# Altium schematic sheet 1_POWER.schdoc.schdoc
size 426 x 302 mm; Symbol: Sheet_A3_Whycan; Device: Sheet_A3; @Project Name: Avaota A1; REV: 1.0; Company: YuzukiHD; Draw By: GloomyGhost; @Update Date: 2024-03-22; @Page No: 3; @Page Count: 13
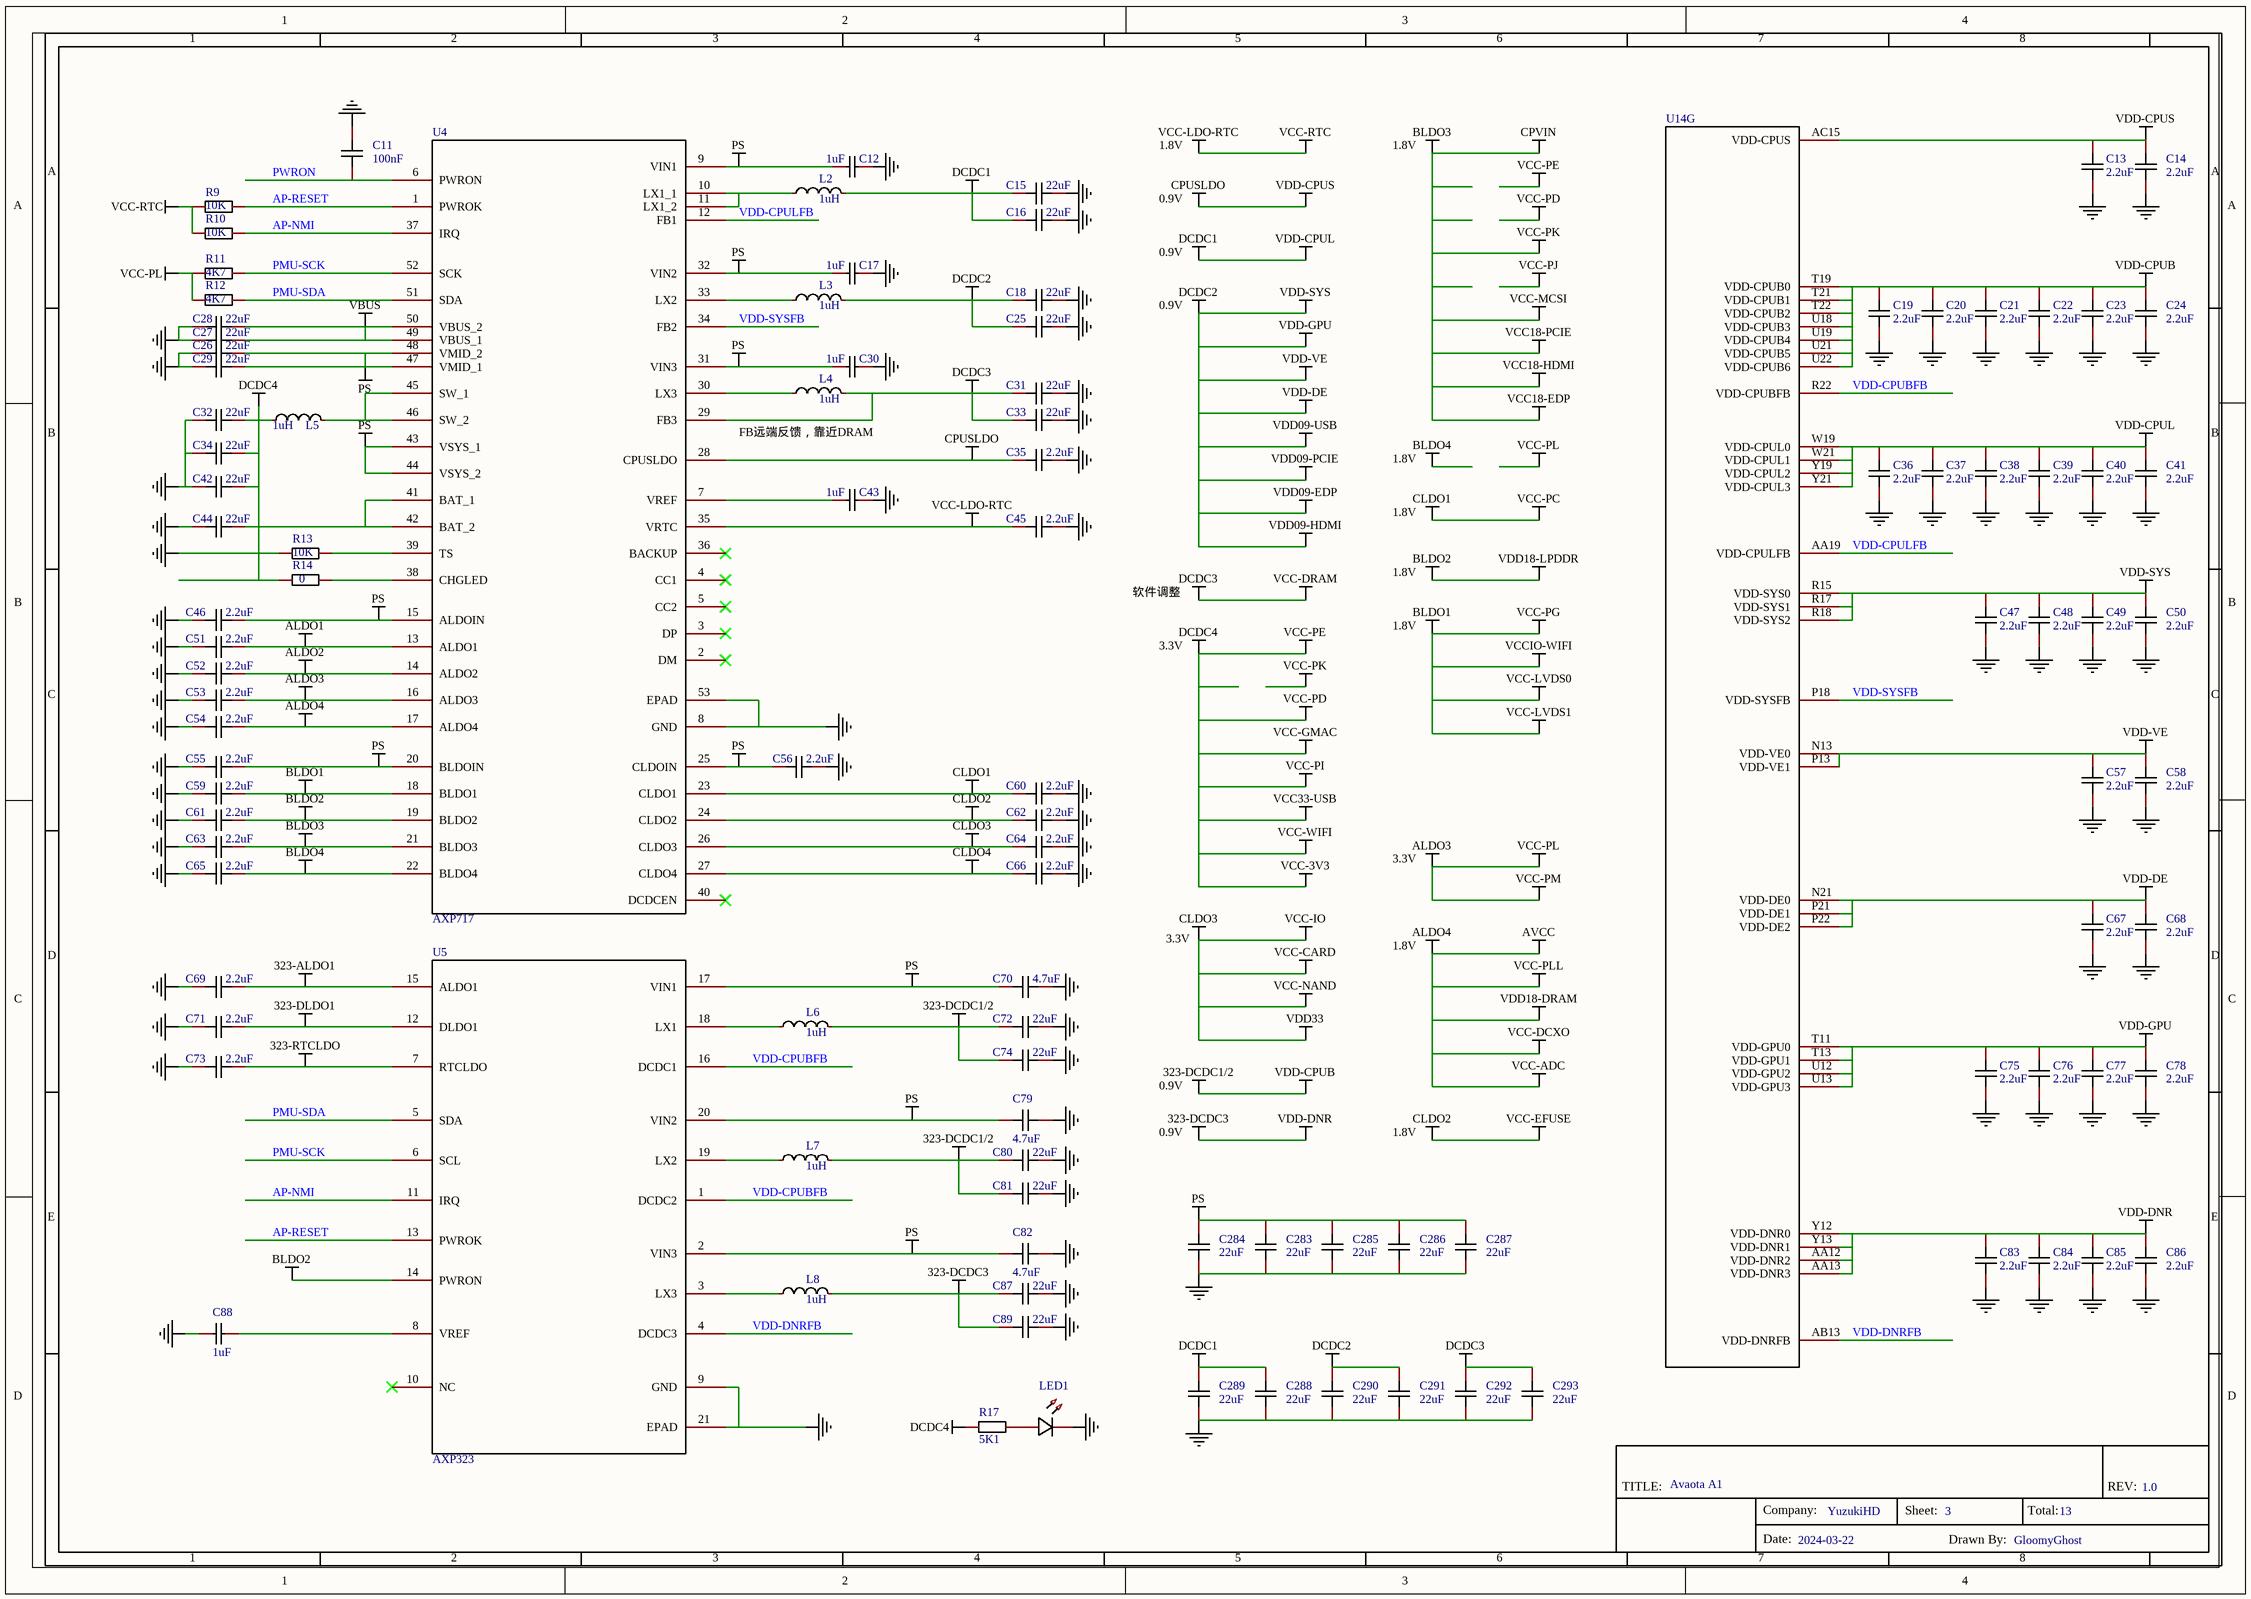
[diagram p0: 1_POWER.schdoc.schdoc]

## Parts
C11  100nF  [c0201 nsk]
C12  1uF  [c0201 nsk]
C13  2.2uF  [c0201 nsk]
C14  2.2uF  [c0201 nsk]
C15  22uF  [c0402-nsk]
C16  22uF  [c0402-nsk]
C17  1uF  [c0201 nsk]
C18  22uF  [c0402-nsk]
C19  2.2uF  [c0201 nsk]
C20  2.2uF  [c0201 nsk]
C21  2.2uF  [c0201 nsk]
C22  2.2uF  [c0201 nsk]
C23  2.2uF  [c0201 nsk]
C24  2.2uF  [c0201 nsk]
C25  22uF  [c0402-nsk]
C26  22uF  [c0402-nsk]
C27  22uF  [C0603-NSK]
C28  22uF  [C0603-NSK]
C29  22uF  [c0402-nsk]
C30  1uF  [c0201 nsk]
C31  22uF  [c0402-nsk]
C32  22uF  [c0402-nsk]
C33  22uF  [c0402-nsk]
C34  22uF  [c0402-nsk]
C35  2.2uF  [c0201 nsk]
C36  2.2uF  [c0201 nsk]
C37  2.2uF  [c0201 nsk]
C38  2.2uF  [c0201 nsk]
C39  2.2uF  [c0201 nsk]
C40  2.2uF  [c0201 nsk]
C41  2.2uF  [c0201 nsk]
C42  22uF  [c0402-nsk]
C43  1uF  [c0201 nsk]
C44  22uF  [C0603-NSK]
C45  2.2uF  [c0201 nsk]
C46  2.2uF  [c0201 nsk]
C47  2.2uF  [c0201 nsk]
C48  2.2uF  [c0201 nsk]
C49  2.2uF  [c0201 nsk]
C50  2.2uF  [c0201 nsk]
C51  2.2uF  [c0201 nsk]
C52  2.2uF  [c0201 nsk]
C53  2.2uF  [c0201 nsk]
C54  2.2uF  [c0201 nsk]
C55  2.2uF  [c0201 nsk]
C56  2.2uF  [c0402-nsk]
C57  2.2uF  [c0201 nsk]
C58  2.2uF  [c0201 nsk]
C59  2.2uF  [c0201 nsk]
C60  2.2uF  [c0201 nsk]
C61  2.2uF  [c0201 nsk]
C62  2.2uF  [c0201 nsk]
C63  2.2uF  [c0201 nsk]
C64  2.2uF  [c0201 nsk]
C65  2.2uF  [c0201 nsk]
C66  2.2uF  [c0201 nsk]
C67  2.2uF  [c0201 nsk]
C68  2.2uF  [c0201 nsk]
C69  2.2uF  [c0201 nsk]
C70  4.7uF  [c0402-nsk]
C71  2.2uF  [c0201 nsk]
C72  22uF  [c0402-nsk]
C73  2.2uF  [c0201 nsk]
C74  22uF  [c0402-nsk]
C75  2.2uF  [c0201 nsk]
C76  2.2uF  [c0201 nsk]
C77  2.2uF  [c0201 nsk]
C78  2.2uF  [c0201 nsk]
C79  4.7uF  [c0402-nsk]
C80  22uF  [c0402-nsk]
C81  22uF  [c0402-nsk]
C82  4.7uF  [c0402-nsk]
C83  2.2uF  [c0201 nsk]
C84  2.2uF  [c0201 nsk]
C85  2.2uF  [c0201 nsk]
C86  2.2uF  [c0201 nsk]
C87  22uF  [c0402-nsk]
C88  1uF  [c0201 nsk]
C89  22uF  [c0402-nsk]
C283  22uF  [C0603-NSK]
C284  22uF  [C0603-NSK]
C285  22uF  [C0603-NSK]
C286  22uF  [C0603-NSK]
C287  22uF  [C0603-NSK]
C288  22uF  [C0603-NSK]
C289  22uF  [C0603-NSK]
C290  22uF  [C0603-NSK]
C291  22uF  [C0603-NSK]
C292  22uF  [C0603-NSK]
C293  22uF  [C0603-NSK]
L2  1uH  [ind-smd_l2.0-w1.6_1]
L3  1uH  [ind-smd_l2.0-w1.6_1]
L4  1uH  [ind-smd_l2.0-w1.6_1]
L5  1uH  [ind-smd_l2.0-w1.6_1]
L6  1uH  [ind-smd_l2.0-w1.6_1]
L7  1uH  [ind-smd_l2.0-w1.6_1]
L8  1uH  [ind-smd_l2.0-w1.6_1]
LED1  LED_0807-RGB  [RGBLED_0807]  (value not drawn)
R9  10K  [r0201 nsk]
R10  10K  [r0201 nsk]
R11  4K7  [r0201 nsk]
R12  4K7  [r0201 nsk]
R13  10K  [r0201 nsk]
R14  0  [r0201 nsk]
R17  5K1  [r0201 nsk]
U4  AXP717  [QFN-52_L6.0-W6.0-P0.40-BL-EP3.4-1]
U5  AXP323  [QFN-20_L3.0-W3.0-P0.40-BL-EP1.5]
U14  T527  [T527-BGA664]  (value not drawn)  (part G of 8)

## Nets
323-ALDO1: C69.1 U5.15(ALDO1)
323-DCDC1/2: C19.1 C20.1 C21.1 C22.1 C23.1 C24.1 C72.2 C74.2 C80.2 C81.2 L6.2 L7.2 U14.T19(VDD-CPUB0) U14.T21(VDD-CPUB1) U14.T22(VDD-CPUB2) U14.U18(VDD-CPUB3) U14.U19(VDD-CPUB4) U14.U21(VDD-CPUB5) U14.U22(VDD-CPUB6)  [also labelled VDD-CPUB]
323-DCDC3: C83.1 C84.1 C85.1 C86.1 C87.2 C89.2 L8.2 U14.AA12(VDD-DNR2) U14.AA13(VDD-DNR3) U14.Y12(VDD-DNR0) U14.Y13(VDD-DNR1)  [also labelled VDD-DNR]
323-DLDO1: C71.1 U5.12(DLDO1)
323-RTCLDO: C73.1 U5.7(RTCLDO)
ALDO1: C51.1 U4.13(ALDO1)
ALDO2: C52.1 U4.14(ALDO2)
ALDO3: C53.1 R11.1 R12.1 U4.16(ALDO3)  [also labelled VCC-PL, VCC-PM]
ALDO4: C54.1 U4.17(ALDO4)  [also labelled AVCC, VCC-ADC, VCC-DCXO, VCC-PLL, VDD18-DRAM]
BLDO1: C59.1 U4.18(BLDO1)  [also labelled VCC-LVDS0, VCC-LVDS1, VCC-PG, VCCIO-WIFI]
BLDO2: C61.1 U4.19(BLDO2) U5.14(PWRON)  [also labelled VDD18-LPDDR]
BLDO3: C63.1 U4.21(BLDO3)  [also labelled CPVIN, VCC-MCSI, VCC-PK, VCC18-EDP, VCC18-HDMI, VCC18-PCIE]
BLDO4: C65.1 U4.22(BLDO4)
CLDO1: C60.2 U4.23(CLDO1)  [also labelled VCC-PC]
CLDO2: C62.2 U4.24(CLDO2)  [also labelled VCC-EFUSE]
CLDO3: C64.2 U4.26(CLDO3)  [also labelled VCC-CARD, VCC-IO, VCC-NAND, VDD33]
CLDO4: C66.2 U4.27(CLDO4)
CPUSLDO: C13.1 C14.1 C35.2 U4.28(CPUSLDO) U14.AC15(VDD-CPUS)  [also labelled VDD-CPUS]
DCDC1: C15.2 C16.2 C36.1 C37.1 C38.1 C39.1 C40.1 C41.1 C288.2 C289.2 L2.2 U14.W19(VDD-CPUL0) U14.W21(VDD-CPUL1) U14.Y19(VDD-CPUL2) U14.Y21(VDD-CPUL3)  [also labelled VDD-CPUL]
DCDC2: C18.2 C25.2 C47.1 C48.1 C49.1 C50.1 C57.1 C58.1 C67.1 C68.1 C75.1 C76.1 C77.1 C78.1 C290.2 C291.2 L3.2 U14.N13(VDD-VE0) U14.N21(VDD-DE0) U14.P13(VDD-VE1) U14.P21(VDD-DE1) U14.P22(VDD-DE2) U14.R15(VDD-SYS0) U14.R17(VDD-SYS1) U14.R18(VDD-SYS2) U14.T11(VDD-GPU0) U14.T13(VDD-GPU1) U14.U12(VDD-GPU2) U14.U13(VDD-GPU3)  [also labelled VDD-DE, VDD-GPU, VDD-SYS, VDD-VE, VDD09-EDP, VDD09-HDMI, VDD09-PCIE, VDD09-USB]
DCDC3: C31.2 C33.2 C292.2 C293.2 L4.2 U4.29(FB3)  [also labelled VCC-DRAM]
DCDC4: C32.1 C34.1 C42.1 L5.1 R14.1 R17.2  [also labelled VCC-3V3, VCC-GMAC, VCC-PD, VCC-PE, VCC-PI, VCC-WIFI, VCC33-USB]
NetC11_2: C11.2 C12.2 C13.2 C14.2 C15.1 C16.1 C17.2 C18.1 C19.2 C20.2 C21.2 C22.2 C23.2 C24.2 C25.1 C26.2 C27.1 C28.1 C29.2 C30.2 C31.1 C32.2 C33.1 C34.2 C35.1 C36.2 C37.2 C38.2 C39.2 C40.2 C41.2 C42.2 C43.2 C44.1 C45.1 C46.2 C47.2 C48.2 C49.2 C50.2 C51.2 C52.2 C53.2 C54.2 C55.2 C56.1 C57.2 C58.2 C59.2 C60.1 C61.2 C62.1 C63.2 C64.1 C65.2 C66.1 C67.2 C68.2 C69.2 C70.1 C71.2 C72.1 C73.2 C74.1 C75.2 C76.2 C77.2 C78.2 C79.1 C80.1 C81.1 C82.1 C83.2 C84.2 C85.2 C86.2 C87.1 C88.2 C89.1 C283.1 C284.1 C285.1 C286.1 C287.1 C288.1 C289.1 C290.1 C291.1 C292.1 C293.1 LED1.2(C) R13.1 U4.8(GND) U4.53(EPAD) U5.9(GND) U5.21(EPAD)
PS: C12.1 C17.1 C26.1 C29.1 C30.1 C46.1 C55.1 C56.2 C70.2 C79.2 C82.2 C283.2 C284.2 C285.2 C286.2 C287.2 U4.9(VIN1) U4.15(ALDOIN) U4.20(BLDOIN) U4.25(CLDOIN) U4.31(VIN3) U4.32(VIN2) U4.43(VSYS_1) U4.44(VSYS_2) U4.47(VMID_1) U4.48(VMID_2) U5.2(VIN3) U5.17(VIN1) U5.20(VIN2)
VBUS: C27.2 C28.2 U4.49(VBUS_1) U4.50(VBUS_2)
VCC-LDO-RTC: C45.2 R9.1 R10.1 U4.35(VRTC)  [also labelled VCC-RTC]
AP-NMI: R10.2 U4.37(IRQ) U5.11(IRQ)
AP-RESET: R9.2 U4.1(PWROK) U5.13(PWROK)
PMU-SCK: R11.2 U4.52(SCK) U5.6(SCL)
PMU-SDA: R12.2 U4.51(SDA) U5.5(SDA)
PWRON: C11.1 U4.6(PWRON)
VDD-CPUBFB: U5.1(DCDC2) U5.16(DCDC1) U14.R22(VDD-CPUBFB)
VDD-CPULFB: U4.12(FB1) U14.AA19(VDD-CPULFB)
VDD-DNRFB: U5.4(DCDC3) U14.AB13(VDD-DNRFB)
VDD-SYSFB: U4.34(FB2) U14.P18(VDD-SYSFB)
NetC43_1: C43.1 U4.7(VREF)
NetC44_2: C44.2 U4.41(BAT_1) U4.42(BAT_2)
NetC88_1: C88.1 U5.8(VREF)
NetL2_1: L2.1 U4.10(LX1_1) U4.11(LX1_2)
NetL3_1: L3.1 U4.33(LX2)
NetL4_1: L4.1 U4.30(LX3)
NetL5_2: L5.2 U4.45(SW_1) U4.46(SW_2)
NetL6_1: L6.1 U5.18(LX1)
NetL7_1: L7.1 U5.19(LX2)
NetL8_1: L8.1 U5.3(LX3)
NetLED1_1: LED1.1(A) R17.1
NetR13_2: R13.2 U4.39(TS)
NetR14_2: R14.2 U4.38(CHGLED)

Not connected (* = marked no-connect by the designer): U4 2(DM)* 3(DP)* 4(CC1)* 5(CC2)* 36(BACKUP)* 40(DCDCEN)*; U5 10(NC)*

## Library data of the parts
C11 = GRM033R60J104KE19D: Manufacturer: muRata(村田); Add into BOM: yes; Tolerance: ±10%; Voltage Rated: 6.3V; Temperature Coefficient: X5R; Description: 容值:100nF;精度:±10%;额定电压:6.3V;材质(温度系数):X5R;
C12 C17 C30 C43 C88 = GRM033R61A105ME44D: Manufacturer: muRata(村田); Add into BOM: yes; Tolerance: ±20%; Voltage Rated: 10V; Temperature Coefficient: X5R; Description: 容值:1uF;精度:±20%;额定电压:10V;材质(温度系数):X5R;
C13 C14 C19-C24 C35-C41 C45-C55 C57-C69 C71 C73 C75-C78 C83-C86 = 0201X225M6R3NT: Manufacturer: FH(风华); Add into BOM: yes; Tolerance: ±20%; Voltage Rated: 6.3V; Temperature Coefficient: X5R; Description: 容值:2.2uF;精度:±20%;额定电压:6.3V;材质(温度系数):X5R;
C15 C16 C18 C25 C26 C29 C31-C34 C42 C72 C74 C80 C81 C87 C89 = GRM155R60J226ME11D: Manufacturer: muRata(村田); Add into BOM: yes; Tolerance: ±20%; Voltage Rated: 6.3V; Temperature Coefficient: X5R; Description: 容值:22uF;精度:±20%;额定电压:6.3V;材质(温度系数):X5R;
C27 C28 C44 C283-C293 = CL10A226MP8NUNE: Manufacturer: SAMSUNG(三星); Add into BOM: yes; Tolerance: ±20%; Voltage Rated: 10V; Temperature Coefficient: X5R; Description: 容值:22uF;精度:±20%;额定电压:10V;材质(温度系数):X5R;
C56 = CL05A225KP5NSNC: Manufacturer: SAMSUNG(三星); Add into BOM: yes; Tolerance: ±10%; Voltage Rated: 10V; Temperature Coefficient: X5R; Description: 容值:2.2uF;精度:±10%;额定电压:10V;材质(温度系数):X5R;
C70 C79 C82 = CL05A475KP5NRNC: Manufacturer: SAMSUNG(三星); Add into BOM: yes; Tolerance: ±10%; Voltage Rated: 10V; Temperature Coefficient: X5R; Description: 容值:4.7uF;精度:±10%;额定电压:10V;材质(温度系数):X5R;
L2-L8 = TFM201610ALM-1R0MTAA: Manufacturer: TDK; Add into BOM: yes; Tolerance: ±20%; Rated Current: 3.1A; Saturation Current (Isat): 4.3A; DC Resistance (DCR): 50mΩ; Description: 电感值:1uH;精度:±20%;额定电流:3.1A;饱和电流(Isat):4.3A;直流电阻(DCR):50mΩ;
LED1 = LED_0807-RGB: Symbol: LED_G; Convert to PCB: yes
R9-R14 R17 = Res_0201: Symbol: 电阻; Convert to PCB: yes
U4 = AXP717B: Add into BOM: yes
U5 = AXP323: Add into BOM: yes
U14 = T527: Add into BOM: yes; SWAP_INFO: (S1+S2+S3+S4+S5+S6+S7+S8+S9); SPLIT_INST: TRUE; Description: Allwinner T527 SoC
